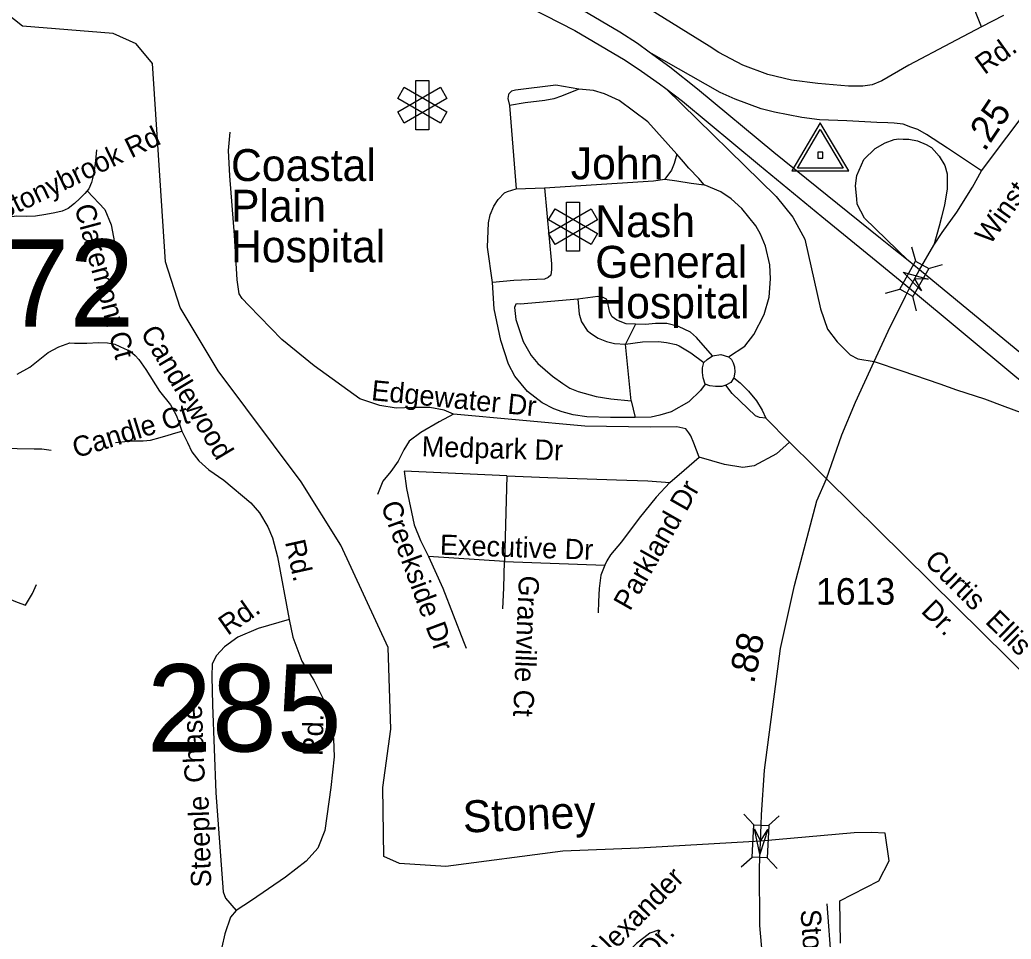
# Model space of a CAD drawing. Extents: x 2220236 to 2384410, y 720751 to 894131.
# Drawn here: x 2336892 to 2341549, y 808960 to 813280 of the extents above; entities that cross this region are included whole.
import ezdxf

# ---------------------------------------------------------------- set-up
doc = ezdxf.new("R2010")
doc.units = 0
doc.layers.add('Default', color=7, linetype='Continuous')

msp = doc.modelspace()

# ---------------------------------------------------------------- linework, layer by layer
at = {"layer": 'Default'}
for p, q in [((2341409.9, 813246.8), (2341329.4, 813447.2)), ((2339192.4, 812876.8), (2339223.2, 812485.3)), ((2339223.2, 812485.3), (2339357, 812491)), ((2341100.2, 812145.5), (2341082, 812212)), ((2341160.1, 812111.3), (2341226.6, 812129.4)), ((2340958.4, 811996.2), (2341024.9, 812014.4)), ((2341104.4, 811912.9), (2341086.2, 811979.4)), ((2339784.5, 811850.4), (2339737.8, 811755.8)), ((2339763, 811490.1), (2339737.8, 811755.8)), ((2339763, 811490.1), (2339782.5, 811411.8)), ((2340395.6, 811407.7), (2340507.4, 811295.7)), ((2339180.5, 811136.6), (2339168.6, 810735)), ((2341844.4, 809973.7), (2340681, 811123.3)), ((2339168.6, 810735), (2338811.8, 810757.3)), ((2339168.6, 810735), (2339639.8, 810717.1)), ((2340339.5, 809496.6), (2340293, 809547.6)), ((2340408.4, 809493.4), (2340459.4, 809539.9)), ((2340281.1, 809299.2), (2340332.1, 809345.7)), ((2340449.1, 809291.4), (2340402.6, 809342.4)), ((2340683, 809126.1), (2340796.2, 807614.3))]:
    msp.add_line(p, q, dxfattribs=at)
for points in [[(2339848.7, 813128.2), (2339793.4, 813168.2), (2339710.8, 813221.2), (2339535, 813325), (2339297.9, 813437.3), (2339074.5, 813526.2), (2338886.1, 813589.8), (2338687, 813647), (2338545.2, 813685.1), (2338367.3, 813723.3), (2338174.6, 813750.8), (2337867.6, 813780.5), (2337452.6, 813816.5), (2337031.2, 813845.4)], [(2336903.3, 813761.7), (2337397.5, 813729.6), (2337829.5, 813695.7), (2338164, 813668.2), (2338341.9, 813642.8), (2338511.3, 813606.7), (2338665.9, 813566.5), (2338860.7, 813507.2), (2339030, 813447.8), (2339287.3, 813337.7), (2339499, 813229.6), (2339736.2, 813089.8), (2339812.4, 813039), (2339897.1, 812979.7), (2339925.9, 812957.6)], [(2338601.3, 809348.4), (2338597.2, 809673.2), (2338635.3, 809947.2), (2338622.2, 810330.7), (2338400.3, 810810.6), (2338213.3, 811108.2), (2337823.3, 811630.5), (2337645.3, 811928.5), (2337576.2, 812142.3), (2337515.3, 813075.2), (2337438.2, 813167.3), (2337330.1, 813215.3), (2336904.2, 813250.5), (2336829.2, 813309.8)], [(2341512.7, 813299.9), (2341409.9, 813246.8), (2341263.6, 813169.5), (2341068.6, 813066.8), (2340940.3, 812993.2), (2340895.8, 812974.4), (2340851.4, 812967.5), (2340784.7, 812967.5), (2340641, 812981.2), (2340516.1, 812996.6), (2340405, 813022.3), (2340288.6, 813066.8), (2340175.8, 813126.7), (2340129.6, 813155.8), (2339855, 813326.1)], [(2341064.6, 812148.8), (2340981.6, 812214.3), (2340934.2, 812251.7), (2340433.2, 812656.2), (2340075, 812954.2), (2339945.8, 813058), (2339848.7, 813128.2)], [(2341408.8, 812570.5), (2341249.8, 812676.1), (2341150.2, 812741.6), (2341110, 812763.9), (2341077.1, 812775.5), (2341041, 812789), (2340998.9, 812794.5), (2340968.8, 812796.3), (2340916.8, 812797.6), (2340776.8, 812805.9), (2340648.7, 812810.4), (2340564.6, 812821.4), (2340436.4, 812845.8), (2340374.1, 812861.1), (2340251.8, 812907.5), (2340181, 812938.7), (2339848.7, 813128.2)], [(2341408.8, 812570.5), (2341647.5, 812886.4), (2341876.8, 813151.5)], [(2339517.4, 812954.7), (2339409.2, 812973.3), (2339219.7, 812949.2), (2339201.6, 812944.8), (2339189.7, 812932.7), (2339187.9, 812928.7), (2339184, 812910.7), (2339192.4, 812876.8)], [(2339517.4, 812954.7), (2339435.9, 812921.8), (2339400, 812909.3), (2339358.1, 812900.8), (2339266.3, 812889.7), (2339192.4, 812876.8)], [(2339978.8, 812649.1), (2339841.2, 812801), (2339708, 812901.1), (2339637.7, 812932.2), (2339587.5, 812947.6), (2339517.4, 812954.7)], [(2339925.9, 812957.6), (2340005.1, 812897), (2340365.8, 812597.5), (2340659.7, 812355.3), (2340914.2, 812148.1), (2341070.4, 812018.8)], [(2339925.9, 812957.6), (2340445.1, 812450), (2340522.3, 812353.1), (2340579.6, 812249.8), (2340653.6, 811922), (2340686.4, 811826.8), (2340730.9, 811767.3), (2340791.9, 811705.5), (2340827.6, 811686.2), (2340904.9, 811675)], [(2338929.9, 811426.1), (2338885.7, 811445.5), (2338817.7, 811458.8), (2338739.7, 811457.8), (2338660.2, 811454.9), (2338582.9, 811466.8), (2338489.2, 811499.5), (2338275.2, 811654.2), (2338123.5, 811777.7), (2337967.4, 811936.9), (2337936.2, 811969.6), (2337922.8, 811991.9), (2337913.9, 812057.3), (2337900.1, 812267.4), (2337878.2, 812547.5), (2337872.3, 812666.5), (2337879.7, 812752.7)], [(2341064.6, 812148.8), (2340860.3, 812347.4), (2340825.7, 812413), (2340823.2, 812438.6), (2340817.2, 812499.9), (2340823.1, 812549), (2340855.8, 812623.3), (2340909.3, 812675.4), (2340956.9, 812702.2), (2340998.5, 812717), (2341020.8, 812720), (2341041.6, 812718.5), (2341068.4, 812718.5), (2341108.5, 812711.1), (2341148.7, 812694.7), (2341173.9, 812679.9), (2341187.3, 812666.5), (2341209.6, 812639.7), (2341236.4, 812595.1), (2341248.3, 812555.6), (2341248.3, 812484.2), (2341234.9, 812410.6), (2341221.5, 812351.9), (2341209.6, 812309.5), (2341185.8, 812220.2)], [(2337253.1, 812669.3), (2337248, 812618), (2337239.5, 812559.8), (2337229.2, 812515.3), (2337217.2, 812486.2), (2337198.4, 812464), (2337174.5, 812440), (2337148.8, 812416), (2337119.7, 812393.8), (2337090.6, 812380.1), (2337056.4, 812373.3), (2337013.7, 812364.7), (2336965.8, 812357.8), (2336923, 812356.1), (2336876.8, 812357.8), (2336842.6, 812352.7), (2336815.3, 812345.9), (2336808.4, 812340.7), (2336785.3, 812329.6)], [(2339978.8, 812649.1), (2339965.4, 812604.7), (2339953.5, 812573.5), (2339922.4, 812531.7)], [(2340106.6, 812504.3), (2340082.2, 812533.6), (2340033.8, 812582.4), (2340010, 812612.7), (2339978.8, 812649.1)], [(2341185.8, 812220.2), (2341224.5, 812280.5), (2341293.7, 812376.2), (2341366.4, 812493.2), (2341408.8, 812570.5)], [(2339357, 812491), (2339868.5, 812523.1), (2339922.4, 812531.7)], [(2339922.4, 812531.7), (2339978.7, 812523.7), (2340045.6, 812511.8), (2340106.6, 812504.3)], [(2337209, 812476.5), (2337292.1, 812388.5), (2337321.8, 812316.2), (2337341.7, 812208.7)], [(2339112.4, 812046.2), (2339088.5, 812211.7), (2339093, 812325.7), (2339100.7, 812363.9), (2339118.1, 812404), (2339139.7, 812436.3), (2339169.3, 812466.7), (2339183.3, 812472.9), (2339223.2, 812485.3)], [(2339357, 812491), (2339389.2, 812133.4), (2339389.7, 812107.4), (2339386, 812079.4), (2339374, 812069.3), (2339356.1, 812061), (2339212.3, 812055.3), (2339112.4, 812046.2)], [(2340220.2, 811695.5), (2340296.9, 811745.7), (2340340, 811800.7), (2340389, 811894.5), (2340411.3, 811976.3), (2340418.8, 812063.3), (2340414.3, 812128.7), (2340395, 812216.5), (2340371.2, 812272.3), (2340348.9, 812311.7), (2340283.5, 812393.5), (2340233.3, 812438.6), (2340185.4, 812470.9), (2340106.6, 812504.3)], [(2341118.1, 812105), (2341185.8, 812220.2)], [(2341118.1, 812105), (2341064.6, 812148.8)], [(2341070.4, 812018.8), (2341118.1, 812105)], [(2342532.7, 810941), (2342391, 811060.7), (2342117.7, 811285.4), (2341995.5, 811382.8), (2341624.9, 811686.1), (2341118.1, 812105)], [(2339782.5, 811411.8), (2339666.6, 811411.8), (2339555.1, 811414.7), (2339491.2, 811423.7), (2339439.1, 811437.1), (2339400.5, 811451.9), (2339345.5, 811480.2), (2339276.3, 811533.7), (2339217.7, 811605.5), (2339187, 811661.1), (2339151.6, 811772.7), (2339119.9, 811922.3), (2339112.4, 812046.2)], [(2340904.9, 811675), (2340970.6, 811816.6), (2341052.5, 811981.6), (2341070.4, 812018.8)], [(2341070.4, 812018.8), (2341565.6, 811607.5), (2341764.6, 811446.4), (2341938, 811303)], [(2339513.3, 811967), (2339241.7, 811943.7), (2339231.6, 811945.6), (2339221.7, 811943.4), (2339215.9, 811927.4), (2339222.4, 811871.4), (2339255.7, 811768), (2339294.5, 811702.5), (2339324.9, 811664.7), (2339393.7, 811605.7), (2339442, 811570.3), (2339476.3, 811548.7), (2339514.5, 811533.2), (2339598.7, 811510.2), (2339668.8, 811499.1), (2339763, 811490.1)], [(2339784.5, 811850.4), (2339740.6, 811851.8), (2339696.3, 811869.2), (2339674.3, 811884.9), (2339664, 811904.9), (2339653.5, 811948.7), (2339647.3, 811966.6), (2339629.1, 811976.3), (2339607.2, 811980.2), (2339513.3, 811967)], [(2339513.3, 811967), (2339520.1, 811897), (2339530.6, 811861.2), (2339557.1, 811819.5), (2339577.1, 811803.9), (2339609.3, 811784.2), (2339647.6, 811768.8), (2339685.8, 811759.1), (2339737.8, 811755.8)], [(2340146.2, 811700.7), (2340071.2, 811787.8), (2340043, 811811.5), (2339986.7, 811838.8), (2339930.5, 811852.1), (2339878.4, 811853.4), (2339830.6, 811848.9), (2339784.5, 811850.4)], [(2339737.8, 811755.8), (2339817.6, 811766.7), (2339891.5, 811767.7), (2339929.5, 811764.1), (2339975.7, 811754.5), (2339989.8, 811748.7), (2340044.1, 811715.5), (2340104.6, 811670.2)], [(2336879.4, 811614.2), (2336939.3, 811648.4), (2337024.8, 811716.9), (2337076.1, 811742.6), (2337127.4, 811761.4), (2337149.7, 811759.7), (2337207.8, 811759.7), (2337262.5, 811763.1), (2337303.6, 811761.4), (2337337.8, 811756.2), (2337358.3, 811746), (2337385.7, 811734), (2337409.6, 811723.7), (2337433.6, 811703.2), (2337450.7, 811684.4), (2337484.9, 811636.4), (2337548.2, 811535.5), (2337599.5, 811470.4), (2337626.9, 811422.5), (2337637.1, 811393.4), (2337652.5, 811347.2)], [(2340104.6, 811670.2), (2340120.4, 811684.4), (2340146.2, 811700.7)], [(2340146.2, 811700.7), (2340184.1, 811707.2), (2340220.2, 811695.5)], [(2340220.2, 811695.5), (2340234.5, 811683.7), (2340242.6, 811667.8), (2340248.9, 811650), (2340251.2, 811623.9), (2340245.4, 811597.9)], [(2340373.8, 809497), (2340376.6, 809543.5), (2340389.5, 809754.2), (2340464.6, 810325.1), (2340531.2, 810621.7), (2340636.2, 811018.8), (2340681, 811123.3), (2340752.6, 811330.1), (2340816.6, 811482.7), (2340904.9, 811675)], [(2340904.9, 811675), (2341035.7, 811630.4), (2341214.1, 811569.4), (2341291.4, 811541.2), (2341423.7, 811499.5), (2341518.8, 811463.1), (2341819.1, 811352.3), (2341938, 811303)], [(2340111.8, 811568.4), (2340101.5, 811598.2), (2340099.2, 811622.1), (2340098.9, 811644.1), (2340104.6, 811670.2)], [(2340245.4, 811597.9), (2340231.7, 811575.7), (2340207.8, 811563.5)], [(2340245.4, 811597.9), (2340275.8, 811574.3), (2340314.2, 811534.9), (2340352.7, 811489.2), (2340379.3, 811445.7), (2340395.6, 811407.7)], [(2340111.8, 811568.4), (2340088.8, 811538.2), (2340033.8, 811484.6), (2339952, 811438.5), (2339898.5, 811422.2), (2339856.9, 811413.2), (2339782.5, 811411.8)], [(2340207.8, 811563.5), (2340190.1, 811557.2), (2340160.1, 811557), (2340133.9, 811560.5), (2340111.8, 811568.4)], [(2340395.6, 811407.7), (2340365.7, 811411.5), (2340347.6, 811419.2), (2340238.4, 811524), (2340207.8, 811563.5)], [(2338929.9, 811426.1), (2338862.5, 811391.4), (2338775.1, 811340.4), (2338721.5, 811299.8), (2338696, 811259.3), (2338668.8, 811205.2), (2338635.3, 811156.8), (2338597.9, 811112.2), (2338572.7, 811050)], [(2340082.8, 811225.1), (2340058, 811290.8), (2340043.6, 811324.7), (2340034.7, 811339.6), (2340020.3, 811357.4), (2339978.3, 811366.9), (2339852.3, 811365.3), (2339546.4, 811369.7), (2338929.9, 811426.1)], [(2337341.2, 811294.1), (2337414.8, 811301), (2337471.2, 811301), (2337505.4, 811304.4), (2337551.6, 811316.4), (2337589.2, 811328.4), (2337625.2, 811338.6), (2337652.5, 811347.2)], [(2337652.5, 811347.2), (2337679.9, 811294.1), (2337700.4, 811249.6), (2337732.9, 811206.8), (2337780.8, 811165.8), (2337850, 811117.3), (2337977.2, 811010.9), (2338017.8, 810963.3), (2338056.6, 810897.9), (2338079.2, 810846.2), (2338102.2, 810756.5), (2338157.9, 810461.2)], [(2336719.5, 811264.2), (2336764, 811267.6), (2336818.7, 811267.6), (2336880.3, 811265.9), (2336958.9, 811264.2), (2336994.9, 811264.2), (2337039.3, 811257.3)], [(2340507.4, 811295.7), (2340447, 811240), (2340341.5, 811183.4), (2340288, 811176), (2340202.5, 811189.6), (2340082.8, 811225.1)], [(2340507.4, 811295.7), (2340624.3, 811178.6), (2340681, 811123.3)], [(2339946, 811106.1), (2340012.9, 811164.1), (2340082.8, 811225.1)], [(2339180.5, 811136.6), (2338697.3, 811158.9), (2338709.2, 811077.1), (2338744.9, 810906), (2338774.6, 810833.1), (2338811.8, 810757.3)], [(2339180.5, 811136.6), (2339372.2, 811129.9), (2339694.8, 811118), (2339842, 811113.5), (2339946, 811106.1)], [(2339946, 811106.1), (2339880.6, 811036.2), (2339801.8, 810938), (2339718.6, 810826.4), (2339666.6, 810765.4), (2339648.7, 810737.2), (2339639.8, 810717.1)], [(2338811.8, 810757.3), (2338878.7, 810608.5), (2338976.8, 810358.6), (2338988.7, 810327.4)], [(2339161.1, 810511.8), (2339165.6, 810610), (2339168.6, 810735)], [(2339639.8, 810717.1), (2339622, 810671), (2339613.1, 810607), (2339610.1, 810546), (2339608.6, 810492.5)], [(2336601.5, 810658.3), (2336740.9, 810601), (2336879.4, 810542.8), (2336918.7, 810529.1), (2336951.2, 810583.9), (2336970.1, 810626.6)], [(2338157.9, 810461.2), (2338012.3, 810419.5), (2337917, 810378.3), (2337853.4, 810333.5), (2337816, 810293.2), (2337796.4, 810253), (2337793.5, 810193.5), (2337796.5, 810061.1), (2337813.7, 809647.4), (2337847.3, 809182), (2337857.6, 809152), (2337908.3, 809094.7)], [(2338157.9, 810461.2), (2338175.3, 810379.3), (2338216.9, 810266.4), (2338272.8, 810177.5), (2338318.7, 810085.6), (2338344.5, 809995.2), (2338366, 809900.5), (2338368.9, 809817.3), (2338353.2, 809671.9), (2338325.6, 809469.6), (2338292.6, 809387.3), (2338237.4, 809326.6), (2338140.2, 809251.4), (2337979.7, 809141.6), (2337908.3, 809094.7)], [(2340486.7, 807629.8), (2340398.6, 808668.7), (2340368.3, 809024.2), (2340367, 809296.1), (2340373.8, 809497)], [(2340746.4, 808940.6), (2340744.3, 809140.6), (2340926.4, 809233.4), (2340975.4, 809327.3), (2340957.4, 809457.9), (2340892.6, 809461.6), (2340811.3, 809459.2), (2340371.7, 809420.3), (2339800.2, 809387.6), (2339442.2, 809373), (2338893.3, 809301.3), (2338676.3, 809315.5), (2338601.3, 809348.4)], [(2337908.3, 809094.7), (2337882.6, 809062.4), (2337855.6, 808984.1), (2337840.4, 808921.8), (2337835.6, 808822), (2337848.1, 808610.2), (2337870.8, 808386.4), (2337923.6, 807752.1)], [(2339892.7, 809002.6), (2339850.9, 808988.1), (2339789.5, 808939.4), (2339716.4, 808866.6), (2339619.6, 808773.4)]]:
    msp.add_lwpolyline(points, dxfattribs=at)
for points in [[(2338813.2, 812763.4), (2338752.4, 812763.4), (2338752.4, 812994.4), (2338813.2, 812994.4)], [(2338698, 812794.8), (2338667.6, 812847.5), (2338867.6, 812962.9), (2338898, 812910.3)], [(2338898, 812847.5), (2338867.6, 812794.8), (2338667.6, 812910.3), (2338698, 812962.9)], [(2340785.7, 812570.5), (2340651.8, 812796.6), (2340518.3, 812570.5)], [(2340759.8, 812582.6), (2340544.3, 812582.6), (2340651.8, 812764.8)], [(2340664.1, 812629.2), (2340664.1, 812657.5), (2340639.8, 812657.5), (2340639.8, 812629.2)], [(2339521.5, 812192.4), (2339460.7, 812192.4), (2339460.7, 812423.4), (2339521.5, 812423.4)], [(2339406.2, 812223.9), (2339375.8, 812276.5), (2339575.9, 812392), (2339606.3, 812339.3)], [(2339606.3, 812276.5), (2339575.9, 812223.9), (2339375.8, 812339.3), (2339406.2, 812392)], [(2341024.9, 812014.4), (2341099.9, 812145.6), (2341161.2, 812110.6), (2341086.2, 811979.4)], [(2341127.3, 812007), (2341041.5, 812093.6), (2341159.1, 812061.4), (2341094.2, 812062.9)], [(2340332.1, 809345.7), (2340339.2, 809496.6), (2340409.7, 809493.3), (2340402.6, 809342.4)], [(2340406.2, 809475.4), (2340368.6, 809359.4), (2340343.1, 809478.7), (2340371.7, 809420.3)]]:
    msp.add_lwpolyline(points, close=True, dxfattribs=at)

# ---------------------------------------------------------------- texts
for s, height, rotation, p in [('Rd.', 95, 35.7643, (2341423.3, 813019.5)), ('.25', 125, 55.9366, (2341423.6, 812656.8)), ('Stonybrook Rd', 95, 25.7212, (2336804.5, 812334.2)), ('Winstead', 95, 54.4149, (2341449.4, 812218.2)), ('Claremont Ct', 95, 285.0681, (2337148.3, 812401)), ('Candlewood', 95, 300.9475, (2337456.2, 811809.1)), ('Edgewater Dr', 95, 354.3467, (2338540.5, 811492.9)), ('Candle Ct', 95, 17.2455, (2337156.4, 811219.5)), ('Medpark Dr', 95, 358.3563, (2338779.1, 811228.6)), ('Parkland Dr', 95, 60.4176, (2339758, 810497.9)), ('Creekside Dr', 95, 290.2737, (2338586.4, 810999.2)), ('Rd.', 95, 282.4991, (2338137.3, 810826.6)), ('Executive Dr', 95, 358.0784, (2338864.2, 810766.6)), ('Curtis  Ellis', 95, 315.3418, (2341136.1, 810731.2)), ('Granville Ct', 95, 267.5646, (2339237.3, 810670.1)), ('Dr.', 95, 315.3418, (2341120.8, 810497.5)), ('Rd.', 95, 35.1633, (2337868.4, 810384.1)), ('.88', 125, 77.3449, (2340340.1, 810156.7)), ('Chase', 95, 92.4432, (2337762.2, 809696)), ('Rd.', 95, 88.7858, (2338314.8, 809819.9)), ('Steeple', 95, 91.8184, (2337791.8, 809204.5)), ('Stoney', 150, 2.3446, (2338975.7, 809460)), ('Alexander', 95, 45.4688, (2339617.2, 808832.7)), ('Stony Creek Dr', 95, 274.276, (2340558.5, 809096.6)), ('Dr.', 95, 50.036, (2339865.9, 808857.1))]:
    msp.add_text(s, height=height, rotation=rotation, dxfattribs=at).set_placement(p)
for s, height, p in [('Coastal', 150, (2337884.2, 812522.3)), ('John', 150, (2339480, 812530.1)), ('Plain', 150, (2337884.2, 812331.3)), ('Nash', 150, (2339595.2, 812258.7)), ('Hospital', 150, (2337884.2, 812140.2)), ('172', 410.1, (2336514.9, 811837.8)), ('General', 150, (2339595.2, 812067.6)), ('Hospital', 150, (2339595.2, 811876.6)), ('1613', 125, (2340632.1, 810531.5)), ('285', 410.1, (2337489.2, 809841.6))]:
    msp.add_text(s, height=height, dxfattribs=at).set_placement(p)

doc.saveas('drawing.dxf')
